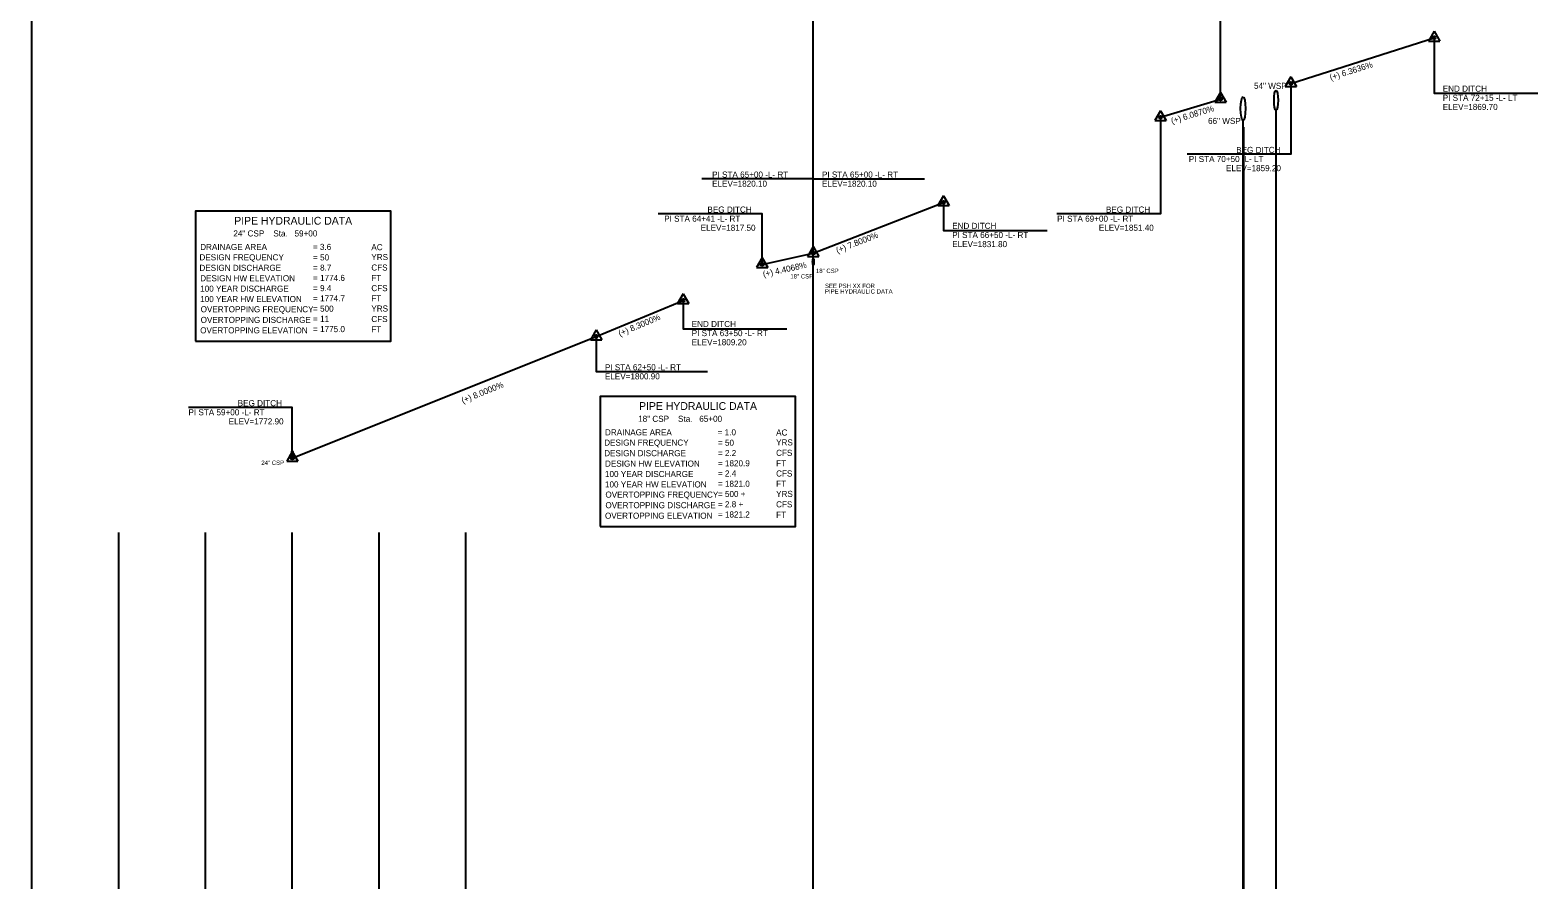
# Model space of a CAD drawing. Extents: x 1025306 to 1036906, y 638983 to 643947.
# Drawn here: x 1029904 to 1031640, y 640868 to 641847 of the extents above; entities that cross this region are included whole.
import ezdxf

# ---------------------------------------------------------------- set-up
doc = ezdxf.new("R2010")
doc.units = 0
for name, color, linetype in [('Default', 7, 'Continuous'), ('Prop PFL Cross Pipe CELL', 7, 'Continuous'), ('Prop PFL Cross Pipe Text CELL', 7, 'Continuous'), ('Prop PFL Pipe Hydraulic Data CELL', 7, 'Continuous'), ('Prop Vertical Profile Ditch Grade Left', 7, 'Continuous'), ('Prop Vertical Profile Ditch Grade Left Label', 7, 'Continuous'), ('Prop Vertical Profile Ditch Grade Right', 7, 'Continuous'), ('Prop Vertical Profile Ditch Grade Right Label', 7, 'Continuous'), ('Prop VPI Ditch Grade Left Label', 7, 'Continuous'), ('Prop VPI Ditch Grade Right Label', 7, 'Continuous'), ('Scratch_Level_0', 7, 'Continuous'), ('Scratch_Level_1', 7, 'Continuous'), ('Scratch_Level_2', 7, 'Continuous'), ('Scratch_Level_3', 7, 'Continuous')]:
    doc.layers.add(name, color=color, linetype=linetype)

msp = doc.modelspace()

# ---------------------------------------------------------------- linework, layer by layer
at = {"layer": 'Default'}
for p, q in [((1031520.6, 641845.4), (1031514.1, 641834.2)), ((1031520.6, 641845.4), (1031527.1, 641834.2)), ((1031514.1, 641834.2), (1031527.1, 641834.2)), ((1031355.6, 641792.9), (1031349.1, 641781.7)), ((1031355.6, 641792.9), (1031362.1, 641781.7)), ((1031274.6, 641774.9), (1031268.1, 641763.7)), ((1031274.6, 641774.9), (1031281.1, 641763.7)), ((1031349.1, 641781.7), (1031362.1, 641781.7)), ((1031205.6, 641753.9), (1031199.1, 641742.7)), ((1031205.6, 641753.9), (1031212.1, 641742.7)), ((1031268.1, 641763.7), (1031281.1, 641763.7)), ((1031199.1, 641742.7), (1031212.1, 641742.7)), ((1030955.6, 641655.9), (1030949.1, 641644.7)), ((1030955.6, 641655.9), (1030962.1, 641644.7)), ((1030949.1, 641644.7), (1030962.1, 641644.7)), ((1030805.6, 641597.4), (1030799.1, 641586.2)), ((1030805.6, 641597.4), (1030812.1, 641586.2)), ((1030746.6, 641584.4), (1030740.1, 641573.2)), ((1030746.6, 641584.4), (1030753.1, 641573.2)), ((1030799.1, 641586.2), (1030812.1, 641586.2)), ((1030740.1, 641573.2), (1030753.1, 641573.2)), ((1030655.6, 641542.9), (1030649.1, 641531.7)), ((1030655.6, 641542.9), (1030662.1, 641531.7)), ((1030649.1, 641531.7), (1030662.1, 641531.7)), ((1030555.6, 641501.4), (1030549.1, 641490.2)), ((1030549.1, 641490.2), (1030562.1, 641490.2)), ((1030555.6, 641501.4), (1030562.1, 641490.2)), ((1030205.6, 641361.4), (1030199.1, 641350.2)), ((1030205.6, 641361.4), (1030212.1, 641350.2)), ((1030199.1, 641350.2), (1030212.1, 641350.2))]:
    msp.add_line(p, q, dxfattribs=at)
for centre, radius in [((1031520.6, 641837.9), 1.75), ((1031520.6, 641837.9), 1.2), ((1031355.6, 641785.4), 1.75), ((1031355.6, 641785.4), 1.2), ((1031274.6, 641767.4), 1.75), ((1031274.6, 641767.4), 1.2), ((1031205.6, 641746.4), 1.75), ((1031205.6, 641746.4), 1.2), ((1030955.6, 641648.4), 1.75), ((1030955.6, 641648.4), 1.2), ((1030746.6, 641576.9), 1.75), ((1030746.6, 641576.9), 1.2), ((1030805.6, 641589.9), 1.75), ((1030805.6, 641589.9), 1.2), ((1030655.6, 641535.4), 1.75), ((1030655.6, 641535.4), 1.2), ((1030555.6, 641493.9), 1.75), ((1030555.6, 641493.9), 1.2), ((1030205.6, 641353.9), 1.75), ((1030205.6, 641353.9), 1.2)]:
    msp.add_circle(centre, radius, dxfattribs=at)
at = {"layer": 'Prop PFL Cross Pipe CELL'}
for centre, major_axis in [((1031300.6, 641756.3), (0, 13.8)), ((1031338.6, 641766), (0, 11.5)), ((1030805.6, 641579.9), (0, 3.75)), ((1030205.6, 641357.2), (0, 5))]:
    msp.add_ellipse(centre, major_axis=major_axis, ratio=0.2, dxfattribs=at)
at = {"layer": 'Prop PFL Pipe Hydraulic Data CELL'}
for points in [[(1030093.9, 641488.4), (1030318.9, 641488.4), (1030318.9, 641638.4), (1030093.9, 641638.4)], [(1030560.2, 641274.9), (1030785.2, 641274.9), (1030785.2, 641424.9), (1030560.2, 641424.9)]]:
    msp.add_lwpolyline(points, close=True, dxfattribs=at)
at = {"layer": 'Prop Vertical Profile Ditch Grade Left'}
msp.add_line((1031355.6, 641785.4), (1031520.6, 641837.9), dxfattribs=at)
at = {"layer": 'Prop Vertical Profile Ditch Grade Right'}
msp.add_line((1031205.6, 641746.4), (1031274.6, 641767.4), dxfattribs=at)
for points in [[(1030746.6, 641576.9), (1030805.6, 641589.9), (1030955.6, 641648.4)], [(1030205.6, 641353.9), (1030555.6, 641493.9), (1030655.6, 641535.4)]]:
    msp.add_lwpolyline(points, dxfattribs=at)
at = {"layer": 'Prop VPI Ditch Grade Left Label'}
for points in [[(1031520.6, 641837.9), (1031520.6, 641774), (1031640.1, 641774)], [(1031355.6, 641785.4), (1031355.6, 641703.8), (1031236.1, 641703.8)]]:
    msp.add_lwpolyline(points, dxfattribs=at)
for centre in [(1031520.6, 641837.9), (1031355.6, 641785.4)]:
    msp.add_circle(centre, 0.5, dxfattribs=at)
at = {"layer": 'Prop VPI Ditch Grade Right Label'}
for points in [[(1031274.6, 641767.4), (1031274.6, 641867.3), (1031394.1, 641867.3)], [(1031205.6, 641746.4), (1031205.6, 641635.1), (1031086.1, 641635.1)], [(1030805.6, 641589.9), (1030805.6, 641675.4), (1030677.3, 641675.4)], [(1030805.6, 641589.9), (1030805.6, 641675.4), (1030933.9, 641675.4)], [(1030955.6, 641648.4), (1030955.6, 641615.9), (1031075.1, 641615.9)], [(1030746.6, 641576.9), (1030746.6, 641635.1), (1030627.1, 641635.1)], [(1030655.6, 641535.4), (1030655.6, 641502.9), (1030775.1, 641502.9)], [(1030555.6, 641493.9), (1030555.6, 641453.4), (1030683.9, 641453.4)], [(1030205.6, 641353.9), (1030205.6, 641412.1), (1030086.1, 641412.1)]]:
    msp.add_lwpolyline(points, dxfattribs=at)
for centre in [(1031274.6, 641767.4), (1031205.6, 641746.4), (1030955.6, 641648.4), (1030746.6, 641576.9), (1030805.6, 641589.9), (1030655.6, 641535.4), (1030555.6, 641493.9), (1030205.6, 641353.9)]:
    msp.add_circle(centre, 0.5, dxfattribs=at)
at = {"layer": 'Scratch_Level_0'}
msp.add_lwpolyline([(1025305.6, 639889.4), (1031301.6, 639889.4), (1031301.6, 641735.1)], dxfattribs=at)
at = {"layer": 'Scratch_Level_1'}
for points in [[(1025305.6, 639889.4), (1031338.6, 639889.4), (1031338.6, 641754.5)], [(1025305.6, 639889.4), (1031300.6, 639889.4), (1031300.6, 641742.5)]]:
    msp.add_lwpolyline(points, dxfattribs=at)
at = {"layer": 'Scratch_Level_2'}
for p, q in [((1030005.6, 639889.4), (1030005.6, 641268.3)), ((1030105.6, 639889.4), (1030105.6, 641268.3)), ((1030205.6, 639889.4), (1030205.6, 641268.3)), ((1030305.6, 639889.4), (1030305.6, 641268.3)), ((1030405.6, 639889.4), (1030405.6, 641268.3))]:
    msp.add_line(p, q, dxfattribs=at)
at = {"layer": 'Scratch_Level_3'}
for p, q in [((1030805.6, 639889.4), (1030805.6, 642751)), ((1029905.6, 639889.4), (1029905.6, 641951.7))]:
    msp.add_line(p, q, dxfattribs=at)

# ---------------------------------------------------------------- texts
at = {"layer": 'Prop PFL Cross Pipe Text CELL'}
for s, height, p in [('54" WSP', 7, (1031313.2, 641779.1)), ('66" WSP', 7, (1031260.3, 641738.7)), ('18" CSP', 5, (1030779.2, 641560.7)), ('18" CSP', 5, (1030808.7, 641567)), ('24" CSP', 5, (1030169.9, 641346))]:
    msp.add_text(s, height=height, dxfattribs=at).set_placement(p)
at = {"layer": 'Prop PFL Pipe Hydraulic Data CELL'}
for s, height, p in [('PIPE HYDRAULIC DATA', 9, (1030138.7, 641622.7)), ('  24" CSP    Sta.   59+00  ', 7, (1030132.5, 641609.1)), ('DRAINAGE AREA', 7, (1030099.5, 641593.5)), ('= 3.6 ', 7, (1030229.3, 641593.6)), ('AC', 7, (1030296.6, 641593.3)), ('DESIGN FREQUENCY', 7, (1030098.6, 641581.6)), ('= 50 ', 7, (1030229.5, 641581.5)), ('YRS', 7, (1030296.6, 641581.9)), ('CFS', 7, (1030296.6, 641569.8)), ('DESIGN DISCHARGE', 7, (1030098.6, 641569.5)), ('DESIGN HW ELEVATION', 7, (1030099.5, 641557.5)), ('= 8.7', 7, (1030229.5, 641569.7)), ('= 1774.6', 7, (1030229.5, 641557.9)), ('FT', 7, (1030296.6, 641557.9)), ('100 YEAR DISCHARGE', 7, (1030099.5, 641545.5)), ('= 9.4', 7, (1030229.5, 641546.1)), ('CFS', 7, (1030296.6, 641546.1)), ('SEE PSH XX FOR', 5, (1030819.1, 641549.7)), ('PIPE HYDRAULIC DATA', 5, (1030819.1, 641543.3)), ('100 YEAR HW ELEVATION', 7, (1030099.5, 641533.5)), ('OVERTOPPING FREQUENCY', 7, (1030100, 641521.8)), ('= 1774.7', 7, (1030229.5, 641534.3)), ('= 500    ', 7, (1030229.5, 641522.5)), ('YRS', 7, (1030296.6, 641522.6)), ('FT', 7, (1030296.6, 641534.3)), ('OVERTOPPING DISCHARGE', 7, (1030100, 641509.5)), ('= 11    ', 7, (1030229.5, 641510.7)), ('CFS', 7, (1030296.6, 641510.5)), ('OVERTOPPING ELEVATION', 7, (1030099.5, 641497.5)), ('= 1775.0', 7, (1030229.5, 641498.9)), ('FT', 7, (1030296.6, 641498.5)), ('PIPE HYDRAULIC DATA', 9, (1030605, 641409.3)), ('DRAINAGE AREA', 7, (1030565.7, 641380)), ('  18" CSP    Sta.   65+00  ', 7, (1030598.7, 641395.6)), ('= 1.0 ', 7, (1030695.5, 641380.1)), ('AC', 7, (1030762.8, 641379.8)), ('DESIGN FREQUENCY', 7, (1030564.8, 641368.2)), ('= 50 ', 7, (1030695.8, 641368)), ('YRS', 7, (1030762.8, 641368.4)), ('DESIGN DISCHARGE', 7, (1030564.8, 641356)), ('= 2.2', 7, (1030695.8, 641356.2)), ('= 1820.9', 7, (1030695.8, 641344.4)), ('CFS', 7, (1030762.8, 641356.4)), ('FT', 7, (1030762.8, 641344.4)), ('DESIGN HW ELEVATION', 7, (1030565.7, 641344)), ('100 YEAR DISCHARGE', 7, (1030565.7, 641332)), ('= 2.4', 7, (1030695.8, 641332.6)), ('CFS', 7, (1030762.8, 641332.6)), ('100 YEAR HW ELEVATION', 7, (1030565.7, 641320)), ('= 1821.0', 7, (1030695.8, 641320.8)), ('FT', 7, (1030762.8, 641320.8)), ('OVERTOPPING FREQUENCY', 7, (1030566.2, 641308.3)), ('OVERTOPPING DISCHARGE', 7, (1030566.2, 641296.1)), ('= 500 +  ', 7, (1030695.8, 641309)), ('= 2.8 + ', 7, (1030695.8, 641297.2)), ('YRS', 7, (1030762.8, 641309.1)), ('CFS', 7, (1030762.8, 641297.1)), ('OVERTOPPING ELEVATION', 7, (1030565.7, 641284)), ('= 1821.2', 7, (1030695.8, 641285.4)), ('FT', 7, (1030762.8, 641285))]:
    msp.add_text(s, height=height, dxfattribs=at).set_placement(p)
at = {"layer": 'Prop Vertical Profile Ditch Grade Left Label'}
msp.add_text('(+) 6.3636%', height=7, rotation=17.6501, dxfattribs=at).set_placement((1031401.7, 641788.7))
at = {"layer": 'Prop Vertical Profile Ditch Grade Right Label'}
for s, rotation, p in [('(+) 6.0870%', 16.9275, (1031218.8, 641738.7)), ('(+) 7.8000%', 21.3058, (1030833.4, 641589.5)), ('(+) 4.4068%', 12.4259, (1030748.4, 641562.2)), ('(+) 8.3000%', 22.5385, (1030582.9, 641493.9)), ('(+) 8.0000%', 21.8014, (1030402, 641416.6))]:
    msp.add_text(s, height=7, rotation=rotation, dxfattribs=at).set_placement(p)
at = {"layer": 'Prop VPI Ditch Grade Left Label'}
for s, p in [('END DITCH', (1031530.6, 641775.8)), ('PI STA 72+15 -L- LT', (1031530.6, 641765.3)), ('ELEV=1869.70', (1031530.6, 641754.8)), ('PI STA 70+50 -L- LT', (1031238.1, 641694.8)), ('BEG DITCH', (1031292.7, 641705.3)), ('ELEV=1859.20', (1031281, 641684.3))]:
    msp.add_text(s, height=7, dxfattribs=at).set_placement(p)
at = {"layer": 'Prop VPI Ditch Grade Right Label'}
for s, p in [('PI STA 65+00 -L- RT', (1030689.1, 641676.9)), ('PI STA 65+00 -L- RT', (1030815.6, 641676.9)), ('ELEV=1820.10', (1030689.1, 641666.4)), ('ELEV=1820.10', (1030815.6, 641666.4)), ('PI STA 64+41 -L- RT', (1030633.9, 641626.1)), ('BEG DITCH', (1030683.7, 641636.6)), ('PI STA 69+00 -L- RT', (1031086.5, 641626.1)), ('BEG DITCH', (1031142.7, 641636.6)), ('ELEV=1817.50', (1030675.9, 641615.6)), ('END DITCH', (1030965.6, 641617.8)), ('PI STA 66+50 -L- RT', (1030965.6, 641607.3)), ('ELEV=1851.40', (1031134.5, 641615.6)), ('ELEV=1831.80', (1030965.6, 641596.8)), ('END DITCH', (1030665.6, 641504.8)), ('PI STA 63+50 -L- RT', (1030665.6, 641494.3)), ('ELEV=1809.20', (1030665.6, 641483.8)), ('PI STA 62+50 -L- RT', (1030565.6, 641455)), ('ELEV=1800.90', (1030565.6, 641444.5)), ('BEG DITCH', (1030142.7, 641413.6)), ('PI STA 59+00 -L- RT', (1030086, 641403.1)), ('ELEV=1772.90', (1030132.3, 641392.6))]:
    msp.add_text(s, height=7, dxfattribs=at).set_placement(p)

doc.saveas('drawing.dxf')
